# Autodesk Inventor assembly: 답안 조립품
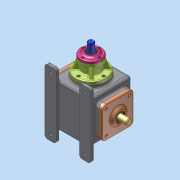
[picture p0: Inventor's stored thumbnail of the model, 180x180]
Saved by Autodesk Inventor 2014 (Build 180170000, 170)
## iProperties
Created: 2026-05
Part Number: 답안 조립품
Document SubType Name: Assembly
Designer: dg
Mass: 6737.06 g
Surface Area: 5034.42 cm^2
Volume: 1833.45 cm^3
Density: 3.67452 g/cm^3
Author: dg
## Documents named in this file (16)
- C:\Users\dg\Desktop\660503V1004\660503V1004\답안 조립품.iam
- C:\Users\dg\Desktop\660503V1004\660503V1004\Imported Components\본체\본체.ipt
- C:\Users\dg\Desktop\660503V1004\660503V1004\Imported Components\종동축\종동축.ipt
- C:\Users\dg\Desktop\660503V1004\660503V1004\Imported Components\테이퍼 롤러 베어링 30204K\테이퍼 롤러 베어링 30204K.ipt
- C:\Users\dg\Desktop\660503V1004\660503V1004\Imported Components\측면 커버\측면 커버.ipt
- C:\Users\dg\Desktop\660503V1004\660503V1004\Imported Components\베벨 기어(종동)\베벨 기어(종동).ipt
- C:\Users\dg\Desktop\660503V1004\660503V1004\Imported Components\칼라\칼라.ipt
- C:\Users\dg\Desktop\660503V1004\660503V1004\Imported Components\베어링 하우징\베어링 하우징.ipt
- C:\Users\dg\Desktop\660503V1004\660503V1004\Imported Components\하우징 커버\하우징 커버.ipt
- C:\Users\dg\Desktop\660503V1004\660503V1004\Imported Components\구동축\구동축.ipt
- C:\Users\dg\Desktop\660503V1004\660503V1004\Imported Components\오일 실 20 35 8\오일 실 20 35 8.ipt
- C:\Users\dg\Desktop\660503V1004\660503V1004\Imported Components\베벨 기어(구동)\베벨 기어(구동).ipt
- C:\Users\dg\Desktop\660503V1004\660503V1004\Imported Components\평행 키 6x6x18\평행 키 6x6x18.ipt
- C:\Users\dg\Desktop\660503V1004\660503V1004\Imported Components\6각 구멍붙이 볼트 M6x12\6각 구멍붙이 볼트 M6x12.ipt
- C:\Users\dg\Desktop\660503V1004\660503V1004\Imported Components\엔드캡\엔드캡.ipt
- C:\Users\dg\Desktop\660503V1004\660503V1004\Imported Components\6각 구멍붙이 볼트 M4x10\6각 구멍붙이 볼트 M4x10.ipt
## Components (19 placed, 4 different names)
1. 하우징 커버:1
2. 구동축:1
3. 6각 구멍붙이 볼트 M6x12:1
4. 6각 구멍붙이 볼트 M4x10:1
5. 6각 구멍붙이 볼트 M4x10:2
6. 6각 구멍붙이 볼트 M4x10:3
7. 6각 구멍붙이 볼트 M4x10:4
8. 6각 구멍붙이 볼트 M6x12:3
9. 6각 구멍붙이 볼트 M6x12:5
10. 6각 구멍붙이 볼트 M6x12:6
11. 6각 구멍붙이 볼트 M6x12:7
12. 6각 구멍붙이 볼트 M6x12:2
13. 6각 구멍붙이 볼트 M6x12:8
14. 6각 구멍붙이 볼트 M6x12:9
15. 6각 구멍붙이 볼트 M6x12:10
16. 6각 구멍붙이 볼트 M6x12:4
17. 6각 구멍붙이 볼트 M6x12:11
18. 6각 구멍붙이 볼트 M6x12:12
19. 6각 구멍붙이 볼트 M6x12:13
